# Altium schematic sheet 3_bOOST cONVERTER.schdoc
size 254 x 203 mm; Symbol: Altium_A; Device: Altium_A; SheetNumber: 1; SheetTotal: 5
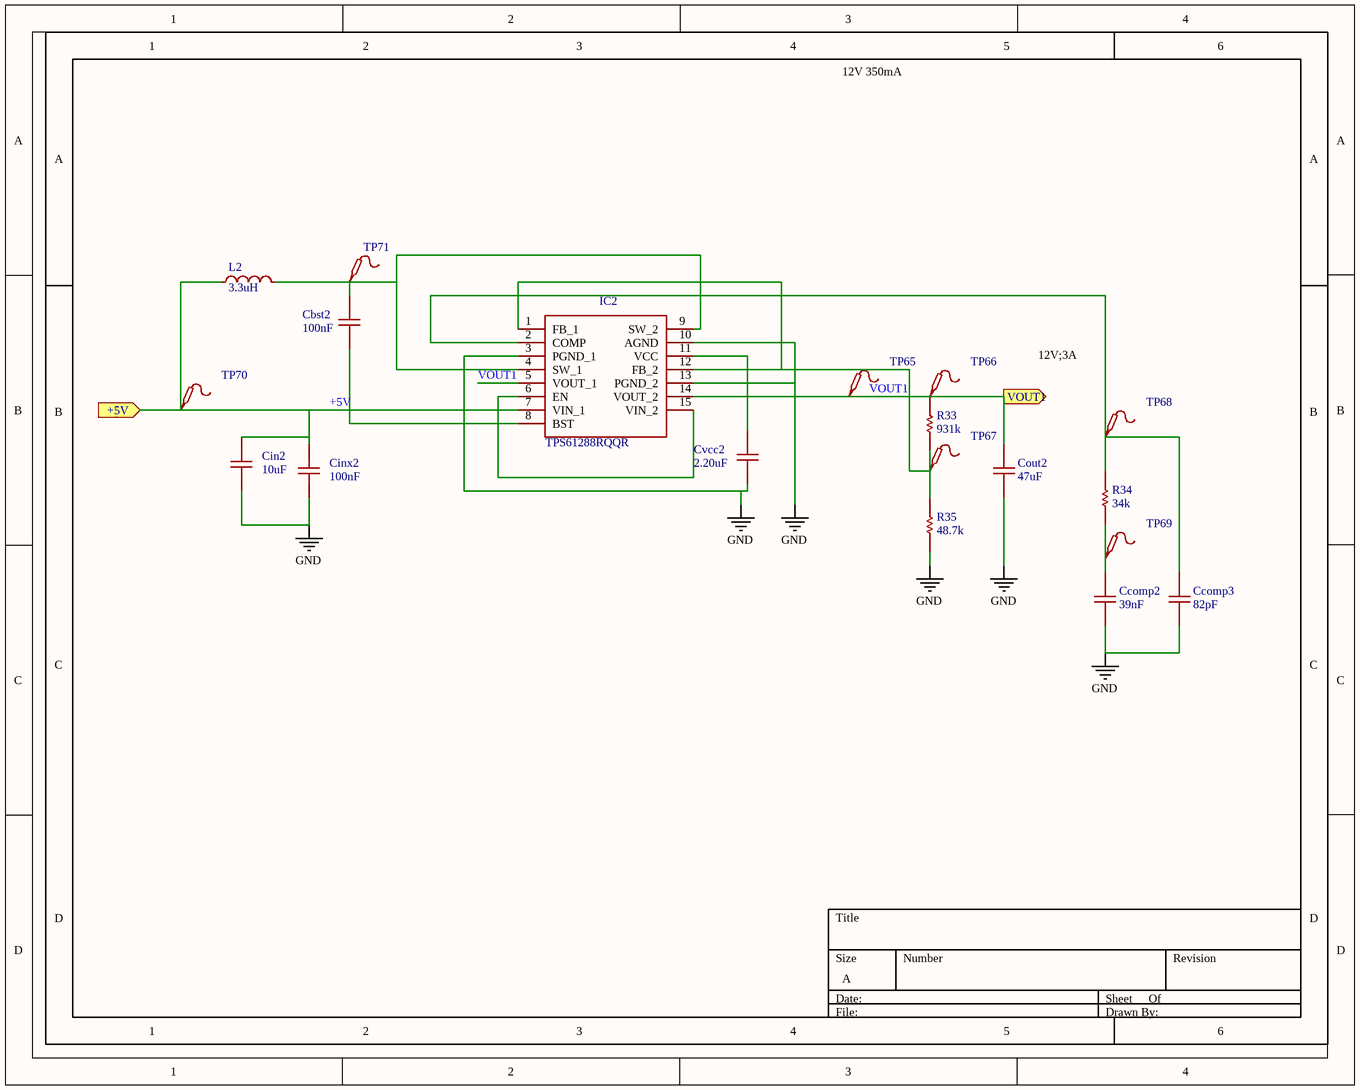
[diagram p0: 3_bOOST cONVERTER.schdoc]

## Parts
Cbst2  100nF  [EMK105 B7104KVHF]  (value not drawn)
Ccomp2  39nF  [C0201]  (value not drawn)
Ccomp3  82pF  [C0402]  (value not drawn)
Cin2  10uF  [C0805]  (value not drawn)
Cinx2  100nF  [EMK105 B7104KVHF]  (value not drawn)
Cout2  47uF  [C1210]  (value not drawn)
Cvcc2  2.20uF  [C0603]  (value not drawn)
IC2  TPS61288RQQR  [TPS61288RQQR]  (value not drawn)
L2  3.3uH  [DR127-3R3-R (L2)]  (value not drawn)
R33  value 931k  [R0603]  (hidden comment: MCR03..PFX1002)
R34  value 34k  [R0603]  (hidden comment: MCR03..PFX1002)
R35  value 48.7k  [R0204]  (hidden comment: MCR03..PFX1002)
TP65  Test-Point  [Test-Point-0.5mm]  (value not drawn)
TP66  Test-Point  [Test-Point-0.5mm]  (value not drawn)
TP67  Test-Point  [Test-Point-0.5mm]  (value not drawn)
TP68  Test-Point  [Test-Point-0.5mm]  (value not drawn)
TP69  Test-Point  [Test-Point-0.5mm]  (value not drawn)
TP70  Test-Point  [Test-Point-0.5mm]  (value not drawn)
TP71  Test-Point  [Test-Point-0.5mm]  (value not drawn)

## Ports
+5V (in), VOUT1 (out)

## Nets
GND: Ccomp2.1 Ccomp3.1 Cin2.1 Cinx2.2 Cout2.1 Cvcc2.1 IC2.3(PGND_1) IC2.10(AGND) IC2.13(PGND_2) R35.2
+5V: Cin2.2 Cinx2.1 IC2.6(EN) IC2.7(VIN_1) IC2.15(VIN_2) L2.2 TP70.1 ; port +5V
VOUT1: Cout2.2 IC2.5(VOUT_1) IC2.14(VOUT_2) R33.2 TP65.1 TP66.1 ; port VOUT1
NetCbst2_1: Cbst2.1 IC2.4(SW_1) IC2.9(SW_2) L2.1 TP71.1
NetCbst2_2: Cbst2.2 IC2.8(BST)
NetCcomp2_2: Ccomp2.2 R34.1 TP69.1
NetCcomp3_2: Ccomp3.2 IC2.2(COMP) R34.2 TP68.1
NetCvcc2_2: Cvcc2.2 IC2.11(VCC)
NetIC2_1: IC2.1(FB_1) IC2.12(FB_2) R33.1 R35.1 TP67.1

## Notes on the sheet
- 12V 350mA
- 12V;3A

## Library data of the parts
Cbst2 Ccomp2 Ccomp3 Cin2 Cinx2 Cout2 Cvcc2 = CAP_0201: Symbol: CAP; Convert to PCB: yes
L2 = L_0402: Symbol: 电感; Add into BOM: yes
R33-R35 = MCR03..PFX1002: Resistor; Symbol: Res1; Origin Footprint 2: AXIAL-0.3; Add into BOM: yes; Origin Footprint 1: RESC1608X55N
TP65-TP71 = Test-Point: Test Point 测试点; Add into BOM: yes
